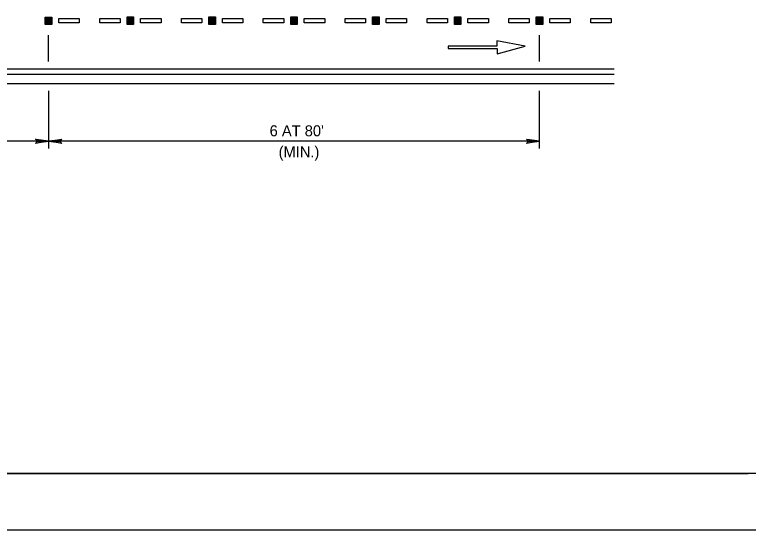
# Model space of a CAD drawing. Extents: x 639362 to 641108, y 298458 to 299646.
# Drawn here: x 639788.7 to 639989.3, y 298457.6 to 298598.6 of the extents above; entities that cross this region are included whole.
import ezdxf

# ---------------------------------------------------------------- set-up
doc = ezdxf.new("R2010")
doc.units = 0
for name, color, linetype in [('1', 7, 'Continuous'), ('2', 7, 'Continuous'), ('3', 7, 'Continuous'), ('PLT-BNDY', 7, 'Continuous')]:
    doc.layers.add(name, color=color, linetype=linetype)

# ---------------------------------------------------------------- blocks, each defined once
blk = doc.blocks.new('RARROW')
at = {"layer": '3'}
blk.add_lwpolyline([(-2.2695, 0.285), (-2.184875, 0.12075), (0, 0), (-2.2695, 0.285), (-2.38575, 0.384625), (0, 0), (-2.183125, -0.108), (-2.262875, -0.2705), (0, 0), (-2.38575, -0.379125), (-2.262875, -0.2705)], dxfattribs=at)

msp = doc.modelspace()

# ---------------------------------------------------------------- linework, layer by layer
at = {"layer": '1'}
for p, q in [((640189.27, 298473.19), (639403.27, 298473.19)), ((639403.27, 298473.19), (639989.27, 298473.19))]:
    msp.add_line(p, q, dxfattribs=at)
at = {"layer": '2'}
for p, q in [((639797.12, 298598), (639798.89, 298598)), ((639797.12, 298595.96), (639797.12, 298598)), ((639797.29, 298597.82), (639798.71, 298597.82)), ((639797.29, 298596.14), (639797.29, 298597.82)), ((639797.47, 298597.64), (639798.54, 298597.64)), ((639797.47, 298596.31), (639797.47, 298597.64)), ((639797.65, 298596.49), (639797.65, 298597.47)), ((639797.65, 298597.47), (639798.36, 298597.47)), ((639797.83, 298597.29), (639798.18, 298597.29)), ((639797.83, 298596.67), (639797.83, 298597.29)), ((639798, 298597.11), (639798, 298596.85)), ((639798.18, 298597.29), (639798.18, 298596.67)), ((639798.36, 298597.47), (639798.36, 298596.49)), ((639798.54, 298597.64), (639798.54, 298596.31)), ((639798.71, 298597.82), (639798.71, 298596.14)), ((639798.89, 298598), (639798.89, 298595.96)), ((639800.79, 298596.4), (639800.79, 298597.6)), ((639800.79, 298597.6), (639806.38, 298597.6)), ((639806.38, 298597.6), (639806.38, 298596.4)), ((639811.98, 298596.4), (639811.98, 298597.6)), ((639811.98, 298597.6), (639817.57, 298597.6)), ((639817.57, 298597.6), (639817.57, 298596.4)), ((639819.48, 298598.02), (639821.25, 298598.02)), ((639819.48, 298595.98), (639819.48, 298598.02)), ((639819.66, 298597.84), (639821.08, 298597.84)), ((639819.66, 298596.15), (639819.66, 298597.84)), ((639819.83, 298597.66), (639820.9, 298597.66)), ((639819.83, 298596.33), (639819.83, 298597.66)), ((639820.01, 298596.51), (639820.01, 298597.48)), ((639820.01, 298597.48), (639820.72, 298597.48)), ((639820.19, 298597.31), (639820.54, 298597.31)), ((639820.19, 298596.69), (639820.19, 298597.31)), ((639820.36, 298597.13), (639820.36, 298596.86)), ((639820.54, 298597.31), (639820.54, 298596.69)), ((639820.72, 298597.48), (639820.72, 298596.51)), ((639820.9, 298597.66), (639820.9, 298596.33)), ((639821.08, 298597.84), (639821.08, 298596.15)), ((639821.25, 298598.02), (639821.25, 298595.98)), ((639823.16, 298596.4), (639823.16, 298597.6)), ((639823.16, 298597.6), (639828.75, 298597.6)), ((639828.75, 298597.6), (639828.75, 298596.4)), ((639834.34, 298596.4), (639834.34, 298597.6)), ((639834.34, 298597.6), (639839.94, 298597.6)), ((639839.94, 298597.6), (639839.94, 298596.4)), ((639841.85, 298598.02), (639843.62, 298598.02)), ((639841.85, 298595.98), (639841.85, 298598.02)), ((639842.02, 298597.84), (639843.44, 298597.84)), ((639842.02, 298596.15), (639842.02, 298597.84)), ((639842.2, 298597.66), (639843.27, 298597.66)), ((639842.2, 298596.33), (639842.2, 298597.66)), ((639842.38, 298596.51), (639842.38, 298597.48)), ((639842.38, 298597.48), (639843.09, 298597.48)), ((639842.56, 298597.31), (639842.91, 298597.31)), ((639842.56, 298596.69), (639842.56, 298597.31)), ((639842.73, 298597.13), (639842.73, 298596.86)), ((639842.91, 298597.31), (639842.91, 298596.69)), ((639843.09, 298597.48), (639843.09, 298596.51)), ((639843.27, 298597.66), (639843.27, 298596.33)), ((639843.44, 298597.84), (639843.44, 298596.15)), ((639843.62, 298598.02), (639843.62, 298595.98)), ((639845.53, 298596.4), (639845.53, 298597.6)), ((639845.53, 298597.6), (639851.12, 298597.6)), ((639851.12, 298597.6), (639851.12, 298596.4)), ((639856.71, 298596.4), (639856.71, 298597.6)), ((639856.71, 298597.6), (639862.3, 298597.6)), ((639862.3, 298597.6), (639862.3, 298596.4)), ((639864.21, 298598.02), (639865.99, 298598.02)), ((639864.21, 298595.98), (639864.21, 298598.02)), ((639864.39, 298597.84), (639865.81, 298597.84)), ((639864.39, 298596.15), (639864.39, 298597.84)), ((639864.57, 298597.66), (639865.63, 298597.66)), ((639864.57, 298596.33), (639864.57, 298597.66)), ((639864.75, 298596.51), (639864.75, 298597.48)), ((639864.75, 298597.48), (639865.46, 298597.48)), ((639864.92, 298597.31), (639865.28, 298597.31)), ((639864.92, 298596.69), (639864.92, 298597.31)), ((639865.1, 298597.13), (639865.1, 298596.86)), ((639865.28, 298597.31), (639865.28, 298596.69)), ((639865.46, 298597.48), (639865.46, 298596.51)), ((639865.63, 298597.66), (639865.63, 298596.33)), ((639865.81, 298597.84), (639865.81, 298596.15)), ((639865.99, 298598.02), (639865.99, 298595.98)), ((639867.89, 298596.4), (639867.89, 298597.6)), ((639867.89, 298597.6), (639873.49, 298597.6)), ((639873.49, 298597.6), (639873.49, 298596.4)), ((639879.08, 298596.4), (639879.08, 298597.6)), ((639879.08, 298597.6), (639884.67, 298597.6)), ((639884.67, 298597.6), (639884.67, 298596.4)), ((639886.58, 298598.02), (639888.36, 298598.02)), ((639886.58, 298595.98), (639886.58, 298598.02)), ((639886.76, 298597.84), (639888.18, 298597.84)), ((639886.76, 298596.15), (639886.76, 298597.84)), ((639886.94, 298597.66), (639888, 298597.66)), ((639886.94, 298596.33), (639886.94, 298597.66)), ((639887.11, 298596.51), (639887.11, 298597.48)), ((639887.11, 298597.48), (639887.82, 298597.48)), ((639887.29, 298597.31), (639887.65, 298597.31)), ((639887.29, 298596.69), (639887.29, 298597.31)), ((639887.47, 298597.13), (639887.47, 298596.86)), ((639887.65, 298597.31), (639887.65, 298596.69)), ((639887.82, 298597.48), (639887.82, 298596.51)), ((639888, 298597.66), (639888, 298596.33)), ((639888.18, 298597.84), (639888.18, 298596.15)), ((639888.36, 298598.02), (639888.36, 298595.98)), ((639890.26, 298596.4), (639890.26, 298597.6)), ((639890.26, 298597.6), (639895.85, 298597.6)), ((639895.85, 298597.6), (639895.85, 298596.4)), ((639901.45, 298596.4), (639901.45, 298597.6)), ((639901.45, 298597.6), (639907.04, 298597.6)), ((639907.04, 298597.6), (639907.04, 298596.4)), ((639908.95, 298598.02), (639910.72, 298598.02)), ((639908.95, 298595.98), (639908.95, 298598.02)), ((639909.13, 298597.84), (639910.55, 298597.84)), ((639909.13, 298596.15), (639909.13, 298597.84)), ((639909.3, 298597.66), (639910.37, 298597.66)), ((639909.3, 298596.33), (639909.3, 298597.66)), ((639909.48, 298596.51), (639909.48, 298597.48)), ((639909.48, 298597.48), (639910.19, 298597.48)), ((639909.66, 298597.31), (639910.01, 298597.31)), ((639909.66, 298596.69), (639909.66, 298597.31)), ((639909.83, 298597.13), (639909.83, 298596.86)), ((639910.01, 298597.31), (639910.01, 298596.69)), ((639910.19, 298597.48), (639910.19, 298596.51)), ((639910.37, 298597.66), (639910.37, 298596.33)), ((639910.55, 298597.84), (639910.55, 298596.15)), ((639910.72, 298598.02), (639910.72, 298595.98)), ((639912.63, 298596.4), (639912.63, 298597.6)), ((639912.63, 298597.6), (639918.22, 298597.6)), ((639918.22, 298597.6), (639918.22, 298596.4)), ((639923.81, 298596.4), (639923.81, 298597.6)), ((639923.81, 298597.6), (639929.41, 298597.6)), ((639929.41, 298597.6), (639929.41, 298596.4)), ((639931.32, 298598.02), (639933.09, 298598.02)), ((639931.32, 298595.98), (639931.32, 298598.02)), ((639931.49, 298597.84), (639932.91, 298597.84)), ((639931.49, 298596.15), (639931.49, 298597.84)), ((639931.67, 298597.66), (639932.74, 298597.66)), ((639931.67, 298596.33), (639931.67, 298597.66)), ((639931.85, 298596.51), (639931.85, 298597.48)), ((639931.85, 298597.48), (639932.56, 298597.48)), ((639932.03, 298597.31), (639932.38, 298597.31)), ((639932.03, 298596.69), (639932.03, 298597.31)), ((639932.2, 298597.13), (639932.2, 298596.86)), ((639932.38, 298597.31), (639932.38, 298596.69)), ((639932.56, 298597.48), (639932.56, 298596.51)), ((639932.74, 298597.66), (639932.74, 298596.33)), ((639932.91, 298597.84), (639932.91, 298596.15)), ((639933.09, 298598.02), (639933.09, 298595.98)), ((639935.01, 298596.4), (639935.01, 298597.6)), ((639935.01, 298597.6), (639940.6, 298597.6)), ((639940.6, 298597.6), (639940.6, 298596.4)), ((639946.21, 298596.4), (639946.21, 298597.6)), ((639946.21, 298597.6), (639951.8, 298597.6)), ((639951.8, 298597.6), (639951.8, 298596.4)), ((639798.89, 298595.96), (639797.12, 298595.96)), ((639798.71, 298596.14), (639797.29, 298596.14)), ((639798.54, 298596.31), (639797.47, 298596.31)), ((639798.36, 298596.49), (639797.65, 298596.49)), ((639798.18, 298596.67), (639797.83, 298596.67)), ((639806.38, 298596.4), (639800.79, 298596.4)), ((639817.57, 298596.4), (639811.98, 298596.4)), ((639821.25, 298595.98), (639819.48, 298595.98)), ((639821.08, 298596.15), (639819.66, 298596.15)), ((639820.9, 298596.33), (639819.83, 298596.33)), ((639820.72, 298596.51), (639820.01, 298596.51)), ((639820.54, 298596.69), (639820.19, 298596.69)), ((639828.75, 298596.4), (639823.16, 298596.4)), ((639839.94, 298596.4), (639834.34, 298596.4)), ((639843.62, 298595.98), (639841.85, 298595.98)), ((639843.44, 298596.15), (639842.02, 298596.15)), ((639843.27, 298596.33), (639842.2, 298596.33)), ((639843.09, 298596.51), (639842.38, 298596.51)), ((639842.91, 298596.69), (639842.56, 298596.69)), ((639851.12, 298596.4), (639845.53, 298596.4)), ((639862.3, 298596.4), (639856.71, 298596.4)), ((639865.99, 298595.98), (639864.21, 298595.98)), ((639865.81, 298596.15), (639864.39, 298596.15)), ((639865.63, 298596.33), (639864.57, 298596.33)), ((639865.46, 298596.51), (639864.75, 298596.51)), ((639865.28, 298596.69), (639864.92, 298596.69)), ((639873.49, 298596.4), (639867.89, 298596.4)), ((639884.67, 298596.4), (639879.08, 298596.4)), ((639888.36, 298595.98), (639886.58, 298595.98)), ((639888.18, 298596.15), (639886.76, 298596.15)), ((639888, 298596.33), (639886.94, 298596.33)), ((639887.82, 298596.51), (639887.11, 298596.51)), ((639887.65, 298596.69), (639887.29, 298596.69)), ((639895.85, 298596.4), (639890.26, 298596.4)), ((639907.04, 298596.4), (639901.45, 298596.4)), ((639910.72, 298595.98), (639908.95, 298595.98)), ((639910.55, 298596.15), (639909.13, 298596.15)), ((639910.37, 298596.33), (639909.3, 298596.33)), ((639910.19, 298596.51), (639909.48, 298596.51)), ((639910.01, 298596.69), (639909.66, 298596.69)), ((639918.22, 298596.4), (639912.63, 298596.4)), ((639929.41, 298596.4), (639923.81, 298596.4)), ((639933.09, 298595.98), (639931.32, 298595.98)), ((639932.91, 298596.15), (639931.49, 298596.15)), ((639932.74, 298596.33), (639931.67, 298596.33)), ((639932.56, 298596.51), (639931.85, 298596.51)), ((639932.38, 298596.69), (639932.03, 298596.69)), ((639940.6, 298596.4), (639935.01, 298596.4)), ((639951.8, 298596.4), (639946.21, 298596.4)), ((639798, 298585.85), (639798, 298593)), ((639928.31, 298590.03), (639920.5, 298591.5)), ((639920.5, 298591.5), (639920.5, 298590.06)), ((639932.2, 298585.85), (639932.2, 298593)), ((639920.5, 298590.06), (639907.26, 298590.06)), ((639907.26, 298590.06), (639907.26, 298589.35)), ((639907.26, 298589.35), (639920.58, 298589.35)), ((639920.58, 298587.91), (639928.31, 298590.03)), ((639920.58, 298589.35), (639920.58, 298587.91)), ((639431.63, 298583.85), (639951.12, 298583.85)), ((639797.99, 298583.85), (639952.64, 298583.85)), ((639431.63, 298582.35), (639951.12, 298582.35)), ((639797.99, 298582.35), (639952.64, 298582.35)), ((639431.63, 298579.85), (639951.12, 298579.85)), ((639797.99, 298579.85), (639952.64, 298579.85)), ((639798, 298577.85), (639798, 298562.02)), ((639932.2, 298562.02), (639932.2, 298577.85)), ((639798, 298564.02), (639585.52, 298564.02)), ((639932.2, 298564.02), (639798, 298564.02))]:
    msp.add_line(p, q, dxfattribs=at)
at = {"layer": 'PLT-BNDY'}
msp.add_lwpolyline([(639362.31, 299051.63), (640203.31, 299051.63), (640203.31, 298457.63), (639362.31, 298457.63)], close=True, dxfattribs=at)

# ---------------------------------------------------------------- block references
at = {"layer": '2', "xscale": 1.5089217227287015, "yscale": 1.5711553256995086}
for p in [(639798, 298564.02), (639932.2, 298564.02)]:
    msp.add_blockref('RARROW', p, dxfattribs=at)
at = {"layer": '2', "xscale": 1.5089217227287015, "yscale": 1.5711553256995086, "rotation": 180}
msp.add_blockref('RARROW', (639798, 298564.02), dxfattribs=at)

# ---------------------------------------------------------------- texts
at = {"layer": '2'}
for s, p in [("6 AT 80'", (639858.44, 298565.39)), ('(MIN.)', (639860.89, 298559.63))]:
    msp.add_text(s, height=3, dxfattribs=at).set_placement(p)

doc.saveas('drawing.dxf')
